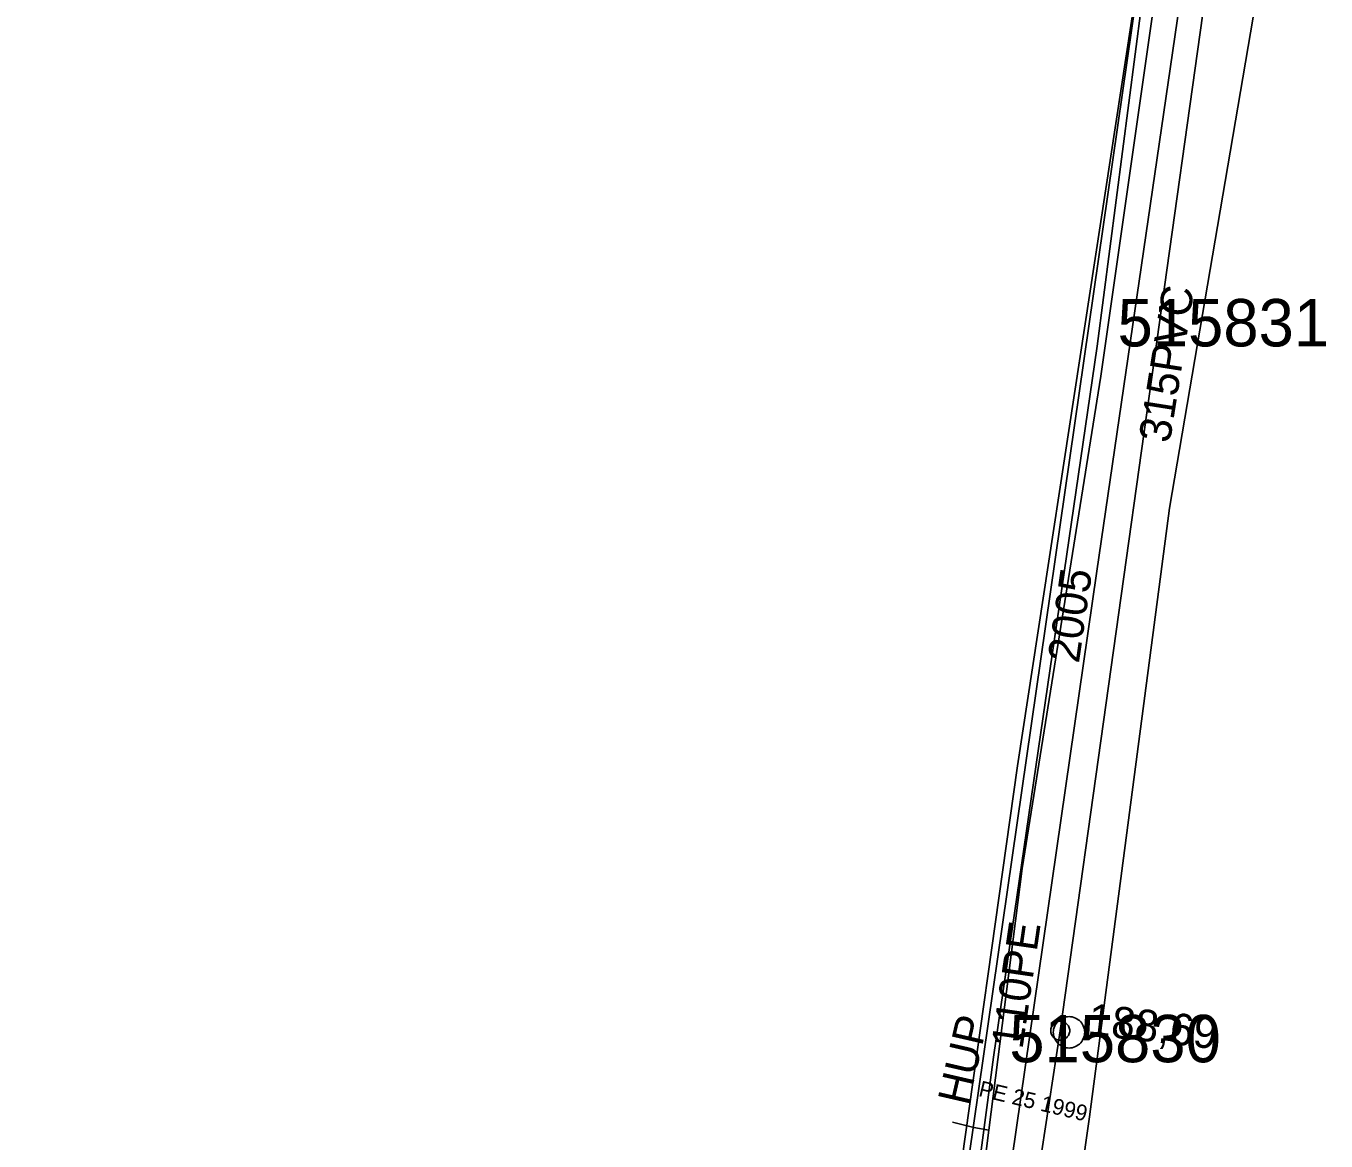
# Model space of a CAD drawing. Extents: x -746464 to -745690, y -1051581 to -1049993.
# Drawn here: x -746044.39 to -746003.26, y -1050883.56 to -1050848.27 of the extents above; entities that cross this region are included whole.
import ezdxf

# ---------------------------------------------------------------- set-up
doc = ezdxf.new("R2010")
doc.units = 0
for name, color, linetype in [('04_CETIN_sdelovaci_podzem', 7, 'Continuous'), ('45_Eltodo_popisy', 7, 'Continuous'), ('45_Eltodo_vedeni_NN_zemni', 7, 'Continuous'), ('48_Prazs_plynarenska_STL', 7, 'Continuous'), ('48_Prazs_plynarenska_STL_popisy', 7, 'Continuous'), ('51_PVaK_kanal_jednotna_overena poloha_rad', 7, 'Continuous'), ('51_PVaK_kanal_objekty', 7, 'Continuous'), ('51_PVaK_kanal_popisy', 7, 'Continuous'), ('51_PVaK_vodovod_overena poloha_rad', 7, 'Continuous'), ('51_PVaK_vodovod_popisy', 7, 'Continuous'), ('55_PREdi_NN', 7, 'Continuous')]:
    doc.layers.add(name, color=color, linetype=linetype)

msp = doc.modelspace()

# ---------------------------------------------------------------- linework, layer by layer
at = {"layer": '04_CETIN_sdelovaci_podzem'}
for points in [[(-746010.74, -1050882.8), (-746008.21, -1050863.53), (-746003.8, -1050837.65), (-746004.77, -1050833.48), (-746007.4, -1050831.64), (-746011.03, -1050830.08)], [(-746018.61, -1050937.66), (-746016.27, -1050921.7), (-746010.74, -1050882.8)]]:
    msp.add_lwpolyline(points, dxfattribs=at)
at = {"layer": '45_Eltodo_vedeni_NN_zemni'}
for points in [[(-746007.693, -1050836.833), (-746010.504, -1050858.401)], [(-746010.504, -1050858.401), (-746013.784, -1050880.907)], [(-746013.784, -1050880.907), (-746016.595, -1050902.163)]]:
    msp.add_lwpolyline(points, dxfattribs=at)
at = {"layer": '48_Prazs_plynarenska_STL'}
for points in [[(-746014.889, -1050832.969), (-746012.94, -1050833.26), (-746011.49, -1050833.41), (-746010.21, -1050833.58), (-746007.28, -1050834), (-746007.6, -1050839.36), (-746008.39, -1050845.39), (-746010.38, -1050859.35), (-746012.87, -1050874.94), (-746013.93, -1050883.22), (-746015.03, -1050891.92)], [(-746013.93, -1050883.22), (-746014.4, -1050883.13), (-746015.079, -1050882.968)]]:
    msp.add_lwpolyline(points, dxfattribs=at)
at = {"layer": '51_PVaK_kanal_jednotna_overena poloha_rad'}
msp.add_line((-746005.67, -1050837.22), (-746011.67, -1050880.07), dxfattribs=at)
msp.add_lwpolyline([(-746011.67, -1050880.07), (-746012.712, -1050886.912), (-746017.23, -1050916.57)], dxfattribs=at)
at = {"layer": '51_PVaK_kanal_objekty'}
for points in [[(-746010.89, -1050880.12), (-746010.9, -1050880.07), (-746010.9, -1050880.02), (-746010.92, -1050879.97), (-746010.94, -1050879.92), (-746010.96, -1050879.87), (-746010.99, -1050879.83), (-746011.02, -1050879.79), (-746011.06, -1050879.75), (-746011.1, -1050879.72), (-746011.14, -1050879.69), (-746011.19, -1050879.67), (-746011.24, -1050879.65), (-746011.29, -1050879.63), (-746011.34, -1050879.63), (-746011.39, -1050879.62), (-746011.44, -1050879.63), (-746011.49, -1050879.63), (-746011.54, -1050879.65), (-746011.59, -1050879.67), (-746011.64, -1050879.69), (-746011.68, -1050879.72), (-746011.72, -1050879.75), (-746011.76, -1050879.79), (-746011.79, -1050879.83), (-746011.82, -1050879.87), (-746011.84, -1050879.92), (-746011.86, -1050879.97), (-746011.88, -1050880.02), (-746011.88, -1050880.07), (-746011.89, -1050880.12), (-746011.88, -1050880.17), (-746011.88, -1050880.22), (-746011.86, -1050880.27), (-746011.84, -1050880.32), (-746011.82, -1050880.37), (-746011.79, -1050880.41), (-746011.76, -1050880.45), (-746011.72, -1050880.49), (-746011.68, -1050880.52), (-746011.64, -1050880.55), (-746011.59, -1050880.57), (-746011.54, -1050880.59), (-746011.49, -1050880.61), (-746011.44, -1050880.61), (-746011.39, -1050880.62), (-746011.34, -1050880.61), (-746011.29, -1050880.61), (-746011.24, -1050880.59), (-746011.19, -1050880.57), (-746011.14, -1050880.55), (-746011.1, -1050880.52), (-746011.06, -1050880.49), (-746011.02, -1050880.45), (-746010.99, -1050880.41), (-746010.96, -1050880.37), (-746010.94, -1050880.32), (-746010.92, -1050880.27), (-746010.9, -1050880.22), (-746010.9, -1050880.17), (-746010.89, -1050880.12)], [(-746011.37, -1050880.07), (-746011.37, -1050880.04), (-746011.376, -1050880.01), (-746011.382, -1050879.98), (-746011.394, -1050879.95), (-746011.412, -1050879.92), (-746011.43, -1050879.896), (-746011.448, -1050879.872), (-746011.472, -1050879.848), (-746011.496, -1050879.83), (-746011.52, -1050879.812), (-746011.55, -1050879.794), (-746011.58, -1050879.782), (-746011.61, -1050879.776), (-746011.64, -1050879.77), (-746011.67, -1050879.77), (-746011.7, -1050879.77), (-746011.73, -1050879.776), (-746011.76, -1050879.782), (-746011.79, -1050879.794), (-746011.82, -1050879.812), (-746011.844, -1050879.83), (-746011.868, -1050879.848), (-746011.892, -1050879.872), (-746011.91, -1050879.896), (-746011.928, -1050879.92), (-746011.946, -1050879.95), (-746011.958, -1050879.98), (-746011.964, -1050880.01), (-746011.97, -1050880.04), (-746011.97, -1050880.07), (-746011.97, -1050880.1), (-746011.964, -1050880.13), (-746011.958, -1050880.16), (-746011.946, -1050880.19), (-746011.928, -1050880.22), (-746011.91, -1050880.244), (-746011.892, -1050880.268), (-746011.868, -1050880.292), (-746011.844, -1050880.31), (-746011.82, -1050880.328), (-746011.79, -1050880.346), (-746011.76, -1050880.358), (-746011.73, -1050880.364), (-746011.7, -1050880.37), (-746011.67, -1050880.37), (-746011.64, -1050880.37), (-746011.61, -1050880.364), (-746011.58, -1050880.358), (-746011.55, -1050880.346), (-746011.52, -1050880.328), (-746011.496, -1050880.31), (-746011.472, -1050880.292), (-746011.448, -1050880.268), (-746011.43, -1050880.244), (-746011.412, -1050880.22), (-746011.394, -1050880.19), (-746011.382, -1050880.16), (-746011.376, -1050880.13), (-746011.37, -1050880.1), (-746011.37, -1050880.07)]]:
    msp.add_lwpolyline(points, dxfattribs=at)
at = {"layer": '51_PVaK_vodovod_overena poloha_rad'}
msp.add_lwpolyline([(-746013.48, -1050886.13), (-746010.51, -1050865.53), (-746007.55, -1050845.21), (-746005.96, -1050833.49), (-746014.36, -1050832.33), (-746021.65, -1050832.4), (-746043.09, -1050830.97), (-746044.39, -1050830.89)], dxfattribs=at)
at = {"layer": '55_PREdi_NN'}
for points in [[(-746011.185, -1050838.221), (-746010.94, -1050835.226), (-746007.578, -1050835.684), (-746017.588, -1050905.078), (-746023.383, -1050946.172), (-746023.937, -1050946.095)], [(-746010.609, -1050835.331), (-746007.578, -1050835.684), (-746008.107, -1050839.561), (-746013.02, -1050871.691), (-746019.935, -1050920.753), (-746024.783, -1050955.321)]]:
    msp.add_lwpolyline(points, dxfattribs=at)

# ---------------------------------------------------------------- texts
at = {"layer": '45_Eltodo_popisy'}
for s, p in [('515831', (-746009.856, -1050858.413)), ('515830', (-746013.281, -1050881.068))]:
    msp.add_text(s, height=1.5, dxfattribs=at).set_placement(p)
at = {"layer": '48_Prazs_plynarenska_STL_popisy'}
for s, height, rotation, p in [('HUP', 1, 77, (-746014.579, -1050882.468)), ('PE 25 1999', 0.5, 346.5809, (-746014.278, -1050882.131))]:
    msp.add_text(s, height=height, rotation=rotation, dxfattribs=at).set_placement(p)
at = {"layer": '51_PVaK_kanal_popisy'}
for s, rotation, p in [('315PVC', 81.0295, (-746008.203, -1050861.496)), ('188,69', 353.4388, (-746010.829, -1050880.189))]:
    msp.add_text(s, height=1, rotation=rotation, dxfattribs=at).set_placement(p)
at = {"layer": '51_PVaK_vodovod_popisy'}
for s, rotation, p in [('2005', 81.7952, (-746011.08, -1050868.464)), ('110PE', 81.7124, (-746012.865, -1050880.676))]:
    msp.add_text(s, height=1, rotation=rotation, dxfattribs=at).set_placement(p)

doc.saveas('drawing.dxf')
